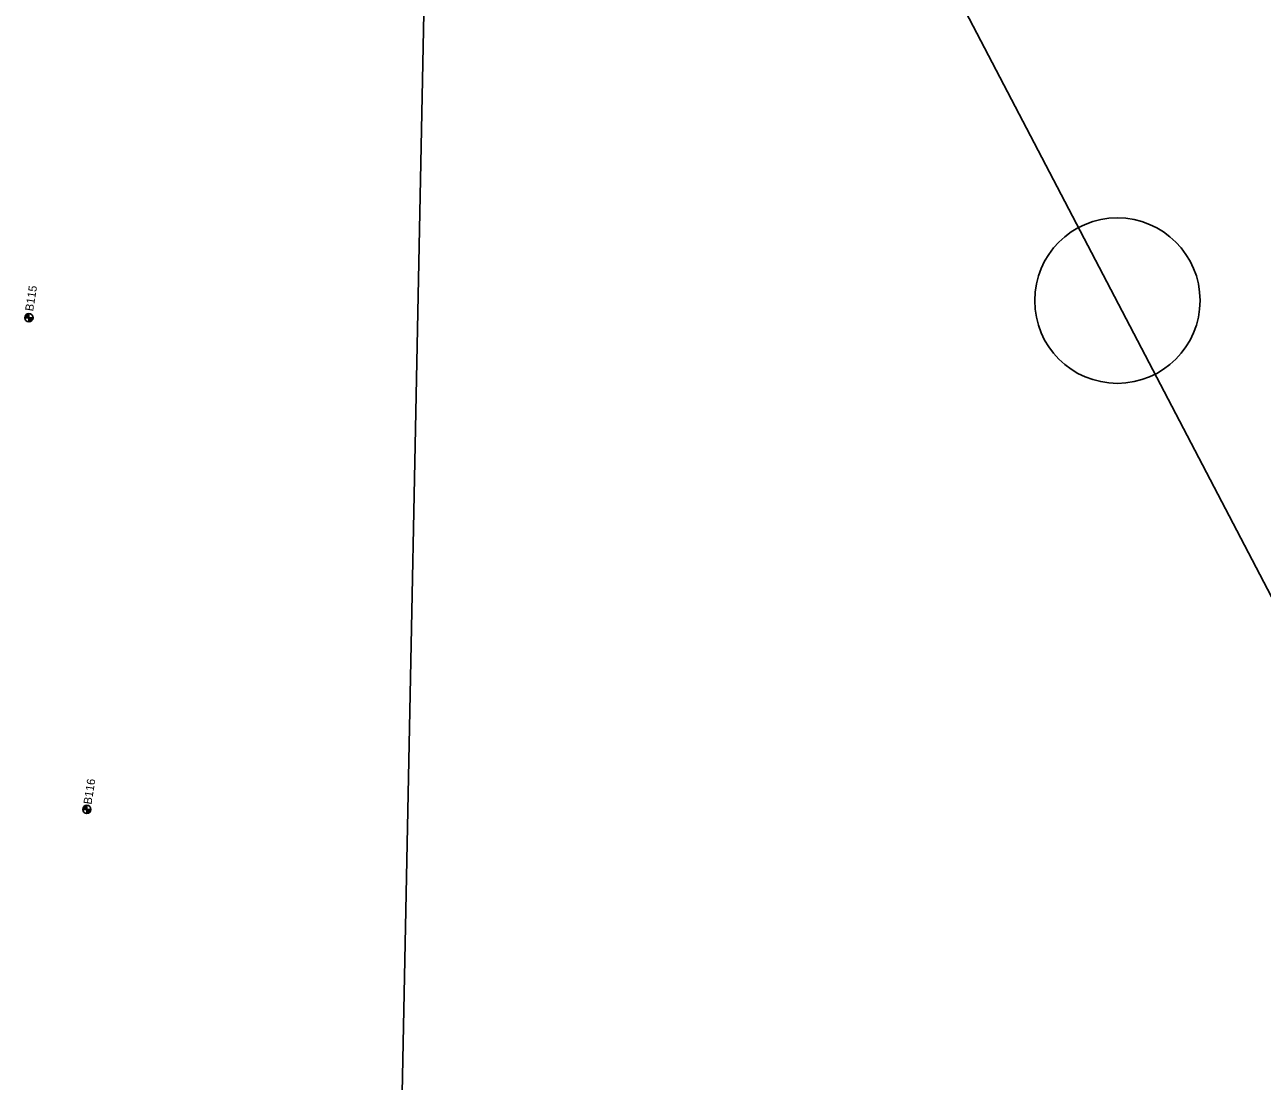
# Model space of a CAD drawing. Extents: x 345549 to 379569, y 127949 to 230467.
# Drawn here: x 355125 to 356627, y 191659 to 192941 of the extents above; entities that cross this region are included whole.
import ezdxf

# ---------------------------------------------------------------- set-up
doc = ezdxf.new("R2010")
doc.units = 0
for name, color, linetype in [('CE-TOPO-CONC-SLAB', 7, 'Continuous'), ('E_RDWY', 7, 'Continuous'), ('E_SOIL_BORE1 [KAPUR_CADDS_LEVELS]', 7, 'Continuous'), ('E_SOIL_BORE2 [KAPUR_CADDS_LEVELS]', 7, 'Continuous'), ('P_MARK', 7, 'Continuous')]:
    doc.layers.add(name, color=color, linetype=linetype)

msp = doc.modelspace()

# ---------------------------------------------------------------- linework, layer by layer
at = {"layer": 'CE-TOPO-CONC-SLAB'}
msp.add_circle((356451.5, 192606.7), 100.4, dxfattribs=at)
at = {"layer": 'E_RDWY'}
for p, q in [((355372.5, 181177.5), (356094.5, 217027.6)), ((358200.3, 189259.9), (355634.1, 194168.3))]:
    msp.add_line(p, q, dxfattribs=at)
at = {"layer": 'P_MARK'}
for p, q in [((355125.2, 192585.9), (355135.2, 192585.9)), ((355130.2, 192590.9), (355130.2, 192580.9)), ((355195.5, 191989.3), (355205.5, 191989.3)), ((355200.5, 191994.3), (355200.5, 191984.3))]:
    msp.add_line(p, q, dxfattribs=at)
for centre in [(355130.2, 192585.9), (355200.5, 191989.3)]:
    msp.add_circle(centre, 5, dxfattribs=at)
for centre, radius, start, end in [((355130.2, 192585.9), 4.5, 89.9869, 179.9869), ((355130.2, 192585.9), 4, 89.9869, 179.9869), ((355130.2, 192585.9), 3.5, 89.9869, 179.9869), ((355130.2, 192585.9), 3, 89.9869, 179.9869), ((355130.2, 192585.9), 2.5, 89.9869, 179.9869), ((355130.2, 192585.9), 2, 89.9869, 179.9869), ((355130.2, 192585.9), 1.5, 89.9869, 179.9869), ((355130.2, 192585.9), 1, 89.9869, 179.9869), ((355130.2, 192585.9), 0.5, 89.9869, 179.9869), ((355130.2, 192585.9), 4.5, 269.9869, 359.9869), ((355130.2, 192585.9), 4, 269.9869, 359.9869), ((355130.2, 192585.9), 3.5, 269.9869, 359.9869), ((355130.2, 192585.9), 3, 269.9869, 359.9869), ((355130.2, 192585.9), 2.5, 269.9869, 359.9869), ((355130.2, 192585.9), 2, 269.9869, 359.9869), ((355130.2, 192585.9), 1.5, 269.9869, 359.9869), ((355130.2, 192585.9), 1, 269.9869, 359.9869), ((355130.2, 192585.9), 0.5, 269.9869, 359.9869), ((355200.5, 191989.3), 4.5, 89.9869, 179.9869), ((355200.5, 191989.3), 4, 89.9869, 179.9869), ((355200.5, 191989.3), 3.5, 89.9869, 179.9869), ((355200.5, 191989.3), 3, 89.9869, 179.9869), ((355200.5, 191989.3), 2.5, 89.9869, 179.9869), ((355200.5, 191989.3), 2, 89.9869, 179.9869), ((355200.5, 191989.3), 1.5, 89.9869, 179.9869), ((355200.5, 191989.3), 1, 89.9869, 179.9869), ((355200.5, 191989.3), 0.5, 89.9869, 179.9869), ((355200.5, 191989.3), 4.5, 269.9869, 359.9869), ((355200.5, 191989.3), 4, 269.9869, 359.9869), ((355200.5, 191989.3), 3.5, 269.9869, 359.9869), ((355200.5, 191989.3), 3, 269.9869, 359.9869), ((355200.5, 191989.3), 2.5, 269.9869, 359.9869), ((355200.5, 191989.3), 2, 269.9869, 359.9869), ((355200.5, 191989.3), 1.5, 269.9869, 359.9869), ((355200.5, 191989.3), 1, 269.9869, 359.9869), ((355200.5, 191989.3), 0.5, 269.9869, 359.9869)]:
    msp.add_arc(centre, radius, start, end, dxfattribs=at)

# ---------------------------------------------------------------- texts
at = {"layer": 'E_SOIL_BORE1 [KAPUR_CADDS_LEVELS]'}
msp.add_text('B115', height=10, rotation=80.9358, dxfattribs=at).set_placement((355135.3, 192593.3))
at = {"layer": 'E_SOIL_BORE2 [KAPUR_CADDS_LEVELS]'}
msp.add_text('B116', height=10, rotation=80.9358, dxfattribs=at).set_placement((355206.1, 191994.8))

doc.saveas('drawing.dxf')
